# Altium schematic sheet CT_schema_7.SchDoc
size 251 x 159 mm
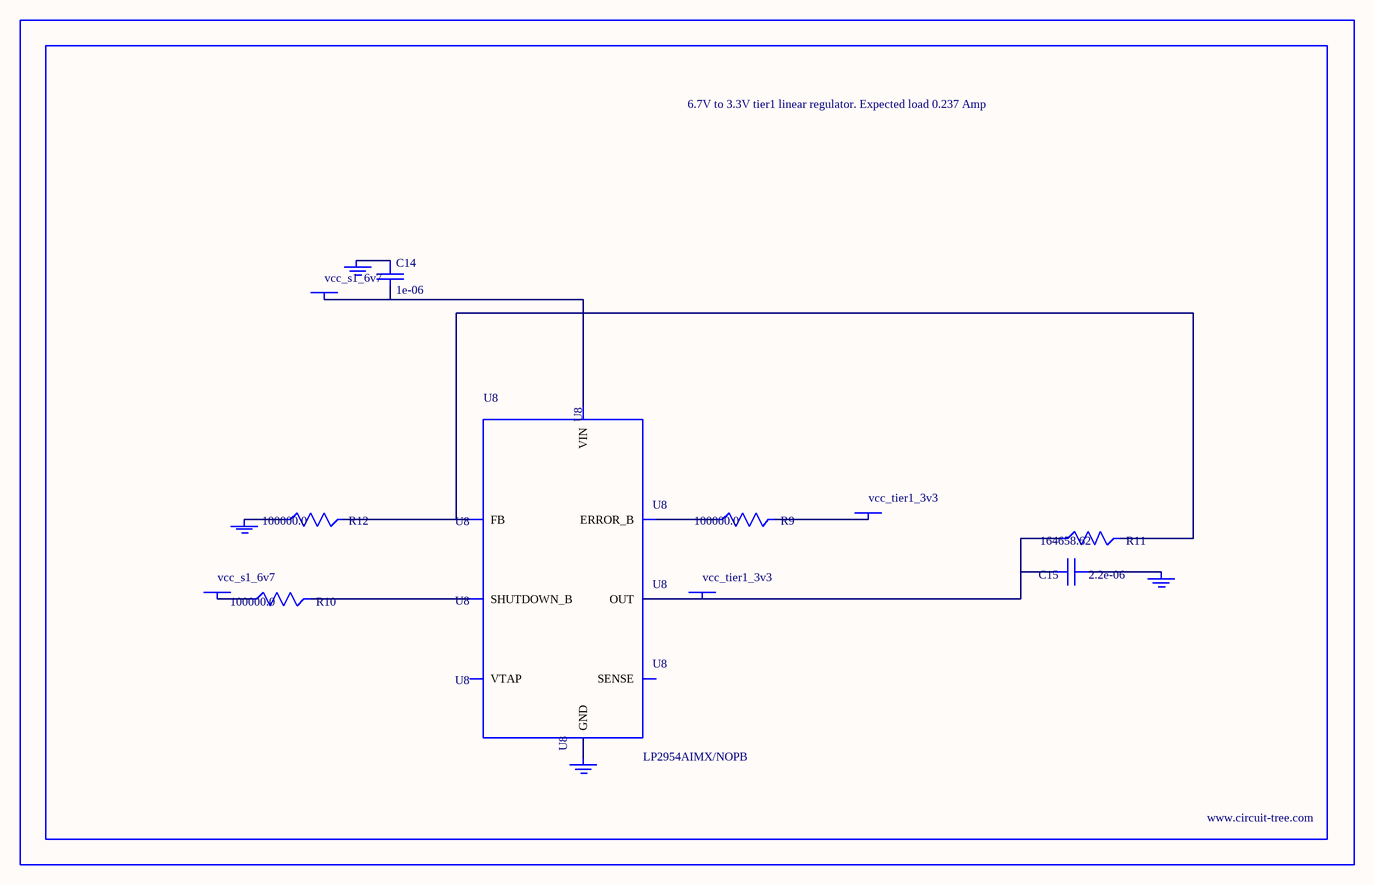
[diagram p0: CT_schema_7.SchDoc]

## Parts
BORDER6  (no value)
C14  1e-06  [EXV-9B]
C15  2.2e-06  [EXV-9B]
GND_INSTANCE_6_0  (no value)
GND_INSTANCE_6_1  (no value)
GND_INSTANCE_6_2  (no value)
GND_INSTANCE_6_3  (no value)
POWER_INSTANCE_6_0  vcc_s1_6v7
POWER_INSTANCE_6_1  vcc_tier1_3v3
POWER_INSTANCE_6_2  vcc_s1_6v7
POWER_INSTANCE_6_3  vcc_tier1_3v3
R9  100000.0  [R0603]
R10  100000.0  [R0603]
R11  164658.62  [R0603]
R12  100000.0  [R0603]
U8  LP2954AIMX/NOPB  [LP2954]

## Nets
NetC14_1: C14.1 GND_INSTANCE_6_2.0(GND)
NetC14_2: C14.2 POWER_INSTANCE_6_2.0(PWR) U8.8(VIN)
NetC15_1: C15.1 GND_INSTANCE_6_0.0(GND)
NetC15_2: C15.2 POWER_INSTANCE_6_3.0(PWR) R11.1 U8.1(OUT)
NetGND_INSTANCE_6_1_0: GND_INSTANCE_6_1.0(GND) R12.1
NetGND_INSTANCE_6_3_0: GND_INSTANCE_6_3.0(GND) U8.4(GND)
NetPOWER_INSTANCE_6_0_0: POWER_INSTANCE_6_0.0(PWR) R10.1
NetPOWER_INSTANCE_6_1_0: POWER_INSTANCE_6_1.0(PWR) R9.2
NetR9_1: R9.1 U8.5(ERROR_B)
NetR10_2: R10.2 U8.3(SHUTDOWN_B)
NetR11_2: R11.2 R12.2 U8.7(FB)

Not connected (* = marked no-connect by the designer): U8 2(SENSE) 6(VTAP)

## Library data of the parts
BORDER6 = BORDER_PAGE6
C14 = EDK105M050A9BAA
C15 = EDK225M050A9BAA
GND_INSTANCE_6_0-GND_INSTANCE_6_3 = GND
POWER_INSTANCE_6_0-POWER_INSTANCE_6_3 = PWR
R9 R10 R12 = RC0603JR-07100KL
R11 = R11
